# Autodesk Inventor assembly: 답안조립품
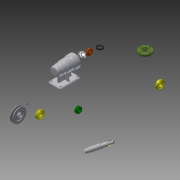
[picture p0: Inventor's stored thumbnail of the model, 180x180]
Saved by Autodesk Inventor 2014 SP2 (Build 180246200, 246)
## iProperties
Created: 2016-06
Part Number: 답안조립품
Document SubType Name: Assembly
Designer: 달님반
Author: 달님반
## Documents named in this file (12)
- C:\Users\달님반\Desktop\460607V1004\답안조립품.iam
- C:\Users\달님반\Desktop\460607V1004\V벨트풀리.ipt
- C:\Users\달님반\Desktop\460607V1004\멈춤나사 M3x8.ipt
- C:\Users\달님반\Desktop\460607V1004\베어링 6004.ipt
- C:\Users\달님반\Desktop\460607V1004\베어링 51202.ipt
- C:\Users\달님반\Desktop\460607V1004\본체.ipt
- C:\Users\달님반\Desktop\460607V1004\볼트 M4 x 12.ipt
- C:\Users\달님반\Desktop\460607V1004\어댑터슬리브.ipt
- C:\Users\달님반\Desktop\460607V1004\오일 실.ipt
- C:\Users\달님반\Desktop\460607V1004\축.ipt
- C:\Users\달님반\Desktop\460607V1004\커버.ipt
- C:\Users\달님반\Desktop\460607V1004\키 5 x 5 x 16.ipt
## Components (2 placed, 2 different names)
1. V벨트풀리:1
2. ISO 4762 M4 x 12:1
